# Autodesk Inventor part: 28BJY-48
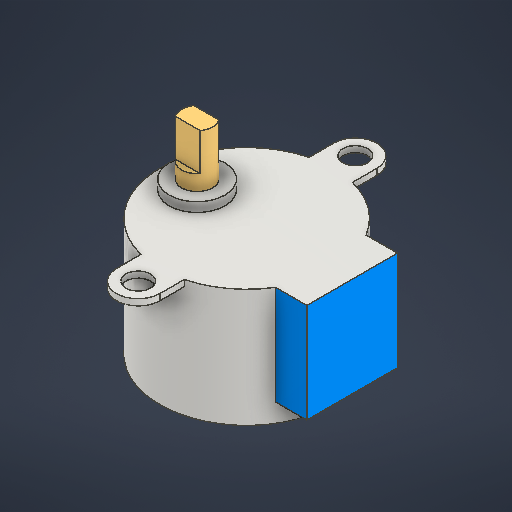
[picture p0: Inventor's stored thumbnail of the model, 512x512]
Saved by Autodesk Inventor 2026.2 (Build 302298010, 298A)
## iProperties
Created: 2026-05
Part Number: 28BJY-48
Material: 강철, 가공됨
Document SubType Name: Modeling
Designer: work
Density: 7.85 g/cm^3
Appearance: 강철
Author: work
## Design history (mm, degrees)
sketch "스케치1"
  geometry: L1 (0, 7.3)-(-17, 7.3); L2 (-17, 7.3)-(-17, -7.3); L3 (-17, -7.3)-(0, -7.3); L4 (0, -7.3)-(0, 7.3); C1 r 14 at (0, 0); 4 further points
  constraints: 8 end point, 2 coincident, 2 parallel, 1 centre point, 1 horizontal, 1 midpoint, 1 perpendicular
  dimensions: "d0" = 28 diameter of C1; "d1" = 14.6 distance of L1.end L2.end; "d2" = 17 distance of L2.end L3.end
extrude "돌출1" new body sketch "스케치1" distance "d3" = 19; taper "d4" = 0 deg
sketch "스케치2"
  geometry: L1 (0, 0)-(-8, 0); L2 (0, -17.5)-(0, 17.5); L3 (3.5, -17.5)-(3.5, 17.5); L4 (-3.5, 17.5)-(-3.5, -17.5); L5 (11.946, -7.3)-(17, -7.3) reference; L6 (17, -7.3)-(17, 7.3) reference; L7 (17, 7.3)-(11.946, 7.3) reference; C1 r 4.5 at (-8, 0); C2 r 2 at (0, 17.5); C3 r 2 at (0, -17.5); A1 r 3.5 centre (0, -17.5) between (-3.5, -17.5) and (3.5, -17.5); A2 r 3.5 centre (0, 17.5) between (3.5, 17.5) and (-3.5, 17.5); A3 r 14 centre (0, 0) between (11.946, 7.3) and (11.946, -7.3) reference; 4 further points
  constraints: 10 end point, 5 centre point, 4 point on circle, 4 tangent, 3 coincident, 1 horizontal, 1 midpoint, 1 parallel, 1 vertical
  dimensions: "d5" = 8 distance of L1.start L1.end; "d6" = 9 diameter of C1; "d7" = 35 distance of L2.start L2.end; "d8" = 7 distance between parallel lines of L4 L3; "d9" = 4 diameter of C2; "d10" = 4 diameter of C3
  node "투영된 루프1"
extrude "돌출2" join sketch "스케치2" distance "d11" = 1; taper "d12" = 0 deg
extrude "돌출3" join sketch "스케치2" distance "d13" = 1.5; taper "d14" = 0 deg
sketch "스케치3"
  geometry: C1 r 2.5 at (0, 0); C2 r 4.5 at (0, 0) reference; C3 r 4.5 at (0, 0) reference; 1 further point
  constraints: 1 centre point, 1 concentric
  dimensions: "d15" = 5 diameter of C1
extrude "돌출4" join sketch "스케치3" distance "d16" = 2.5; taper "d17" = 0 deg
sketch "스케치4"
  geometry: L1 (-2.5, 0)-(2.5, 0); L2 (-2, 1.5)-(2, 1.5); L3 (-2, -1.5)-(2, -1.5); A1 r 2.5 centre (0, 0) between (-2.5, 0) and (2.5, 0) reference; 5 further points
  constraints: 6 end point, 4 point on circle, 2 horizontal, 2 midpoint, 2 symmetric about line
  dimensions: "d18" = 5 distance of L1.start L1.end; "d19" = 3 distance of point (0, -1.5) point (0, 1.5)
extrude "돌출5" join sketch "스케치4" distance "d20" = 6; taper "d21" = 0 deg
sketch "스케치5"
  geometry: L1 (11.946, 7.3)-(17, 7.3) reference; L2 (17, -7.3)-(11.946, -7.3) reference; L3 (17, 7.3)-(17, -7.3) reference; A1 r 14 centre (0, 0) between (11.946, 7.3) and (11.946, -7.3) reference; 3 further points
  constraints: 1 coincident, 3 other
extrude "돌출6" cut sketch "스케치5" distance "d22" = 3; taper "d23" = 0 deg
node "솔리드1"
node "투영된 루프2"
node "투영된 루프3"
node "투영된 루프4"
